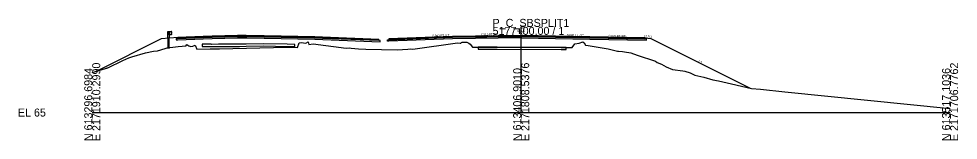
# Model space of a CAD drawing. Extents: x -26 to 1303, y -3010 to 12023.
# Drawn here: x -25.7 to 302.8, y 2990.3 to 3032.8 of the extents above; entities that cross this region are included whole.
import ezdxf

# ---------------------------------------------------------------- set-up
doc = ezdxf.new("R2010")
doc.units = 0
for name, color, linetype in [('RD_GPK_XS_Cell', 7, 'Continuous'), ('RD_PD_Final_TrvlWay', 7, 'Continuous'), ('RD_XS_Base', 7, 'Continuous'), ('RD_XS_ExGround', 7, 'Continuous'), ('RD_XS_ExPaveRet', 7, 'Continuous'), ('RD_XS_GR', 7, 'Continuous'), ('RD_XS_Greenside', 7, 'Continuous'), ('RD_XS_Pave', 7, 'Continuous'), ('RD_XS_PaveOvlay_CP', 7, 'Continuous'), ('RD_XS_TieSlope', 7, 'Continuous'), ('RD_XS_TX_Elev_EX', 7, 'Continuous'), ('RD_XS_TX_Elev_PR', 7, 'Continuous'), ('RD_XS_TX_ShdSlope', 7, 'Continuous'), ('RD_XS_TX_Slope', 7, 'Continuous')]:
    doc.layers.add(name, color=color, linetype=linetype)

msp = doc.modelspace()

# ---------------------------------------------------------------- linework, layer by layer
at = {"layer": 'RD_GPK_XS_Cell'}
for p, q in [((150, 3000), (150, 3030)), ((0, 3000), (150, 3000)), ((150, 3000), (300, 3000))]:
    msp.add_line(p, q, dxfattribs=at)
at = {"layer": 'RD_PD_Final_TrvlWay'}
for p, q in [((26.94, 3026.03), (26.44, 3025.99)), ((26.44, 3025.99), (26.44, 3022.43)), ((26.94, 3022.43), (26.94, 3026.03))]:
    msp.add_line(p, q, dxfattribs=at)
at = {"layer": 'RD_XS_Base'}
for p, q in [((29.75, 3025.95), (29.38, 3025.93)), ((29.38, 3025.93), (29.38, 3025.8)), ((29.38, 3025.8), (29.38, 3025.43)), ((29.88, 3025.95), (29.75, 3025.95)), ((38.75, 3026.31), (29.88, 3025.95)), ((29.88, 3025.45), (38.75, 3025.81)), ((41.88, 3026.43), (38.75, 3026.31)), ((38.75, 3025.81), (41.88, 3025.93)), ((50.75, 3026.61), (41.88, 3026.43)), ((41.88, 3025.93), (50.75, 3026.11)), ((53.88, 3026.67), (50.75, 3026.61)), ((50.75, 3026.11), (53.88, 3026.17)), ((53.88, 3026.79), (53.88, 3026.83)), ((53.88, 3026.83), (53.88, 3026.66)), ((53.88, 3026.67), (53.88, 3026.79)), ((53.88, 3026.54), (53.88, 3026.67)), ((60.14, 3026.55), (53.88, 3026.67)), ((53.88, 3026.66), (53.88, 3026.17)), ((53.88, 3026.17), (53.88, 3026.54)), ((53.88, 3026.17), (60.14, 3026.05)), ((77.88, 3026.19), (60.14, 3026.55)), ((60.14, 3026.05), (77.88, 3025.69)), ((80.49, 3026.09), (77.88, 3026.19)), ((100.21, 3025.3), (80.49, 3026.09)), ((103.74, 3025.46), (126, 3026.35)), ((126, 3025.85), (103.74, 3024.96)), ((126, 3026.35), (150.01, 3026.66)), ((126, 3026.35), (126, 3026.35)), ((150.01, 3026.16), (126, 3025.85)), ((126, 3025.85), (126, 3025.85)), ((150, 3026.66), (150, 3026.82)), ((150, 3026.82), (150, 3026.82)), ((150, 3026.82), (150, 3026.82)), ((150, 3026.82), (150, 3026.16)), ((150, 3026.66), (150, 3026.66)), ((162, 3026.42), (150, 3026.66)), ((150, 3026.66), (150, 3026.66)), ((150, 3026.66), (150, 3026.16)), ((150, 3026.16), (150, 3026.16)), ((150, 3026.16), (162, 3025.92)), ((174, 3026.18), (162, 3026.42)), ((162, 3026.42), (162, 3026.42)), ((162, 3025.92), (162, 3025.92)), ((162, 3025.92), (174, 3025.68)), ((193.3, 3025.8), (174, 3026.18)), ((174, 3026.18), (174, 3026.18)), ((193.8, 3025.79), (193.3, 3025.8)), ((193.3, 3025.8), (193.3, 3025.8)), ((193.8, 3025.29), (193.8, 3025.79)), ((193.8, 3025.79), (193.8, 3025.79)), ((29.38, 3025.43), (29.75, 3025.45)), ((29.75, 3025.45), (29.88, 3025.45)), ((77.88, 3025.69), (80.62, 3025.58)), ((80.62, 3025.58), (100.71, 3024.78)), ((100.34, 3025.29), (100.21, 3025.3)), ((100.71, 3025.28), (100.34, 3025.29)), ((100.71, 3025.15), (100.71, 3025.28)), ((100.71, 3024.78), (100.71, 3025.15)), ((103.24, 3025.44), (103.74, 3025.46)), ((103.24, 3024.94), (103.24, 3025.44)), ((103.24, 3025.44), (103.24, 3025.44)), ((103.74, 3024.96), (103.24, 3024.94)), ((103.24, 3024.94), (103.24, 3024.94)), ((103.24, 3024.94), (103.24, 3024.94)), ((103.74, 3025.46), (103.74, 3025.46)), ((103.74, 3024.96), (103.74, 3024.96)), ((174, 3025.68), (174, 3025.68)), ((174, 3025.68), (193.8, 3025.29))]:
    msp.add_line(p, q, dxfattribs=at)
at = {"layer": 'RD_XS_ExGround'}
msp.add_lwpolyline([(0, 3014.08), (4.65, 3015.43), (5.02, 3015.52), (5.09, 3015.55), (5.24, 3015.64), (5.45, 3015.7), (10.75, 3018.23), (12.84, 3019.16), (13.52, 3019.4), (13.83, 3019.51), (18.57, 3020.96), (21.41, 3021.47), (22.76, 3021.64), (25.49, 3022.44), (26.17, 3022.68), (29.08, 3023.06), (30.02, 3023.11), (32.83, 3023.34), (32.86, 3023.46), (33.13, 3023.79), (33.77, 3023.4), (34.47, 3023.08), (35.18, 3023.19), (36, 3023.59), (36.62, 3022.23), (41.25, 3022.34), (42.12, 3022.34), (44.54, 3022.33), (68.1, 3022.92), (70.89, 3022.85), (71.83, 3022.83), (72.33, 3024.47), (73.09, 3024.48), (74.65, 3024.34), (75.55, 3024.74), (75.74, 3023.81), (77.2, 3024.04), (88.77, 3022.6), (89.85, 3022.63), (90.6, 3022.54), (93.1, 3022.37), (95.69, 3022.14), (106.62, 3021.94), (110.36, 3022.15), (111.14, 3022.26), (112.1, 3022.21), (127.78, 3024.42), (128.61, 3024.35), (128.77, 3024.35), (128.81, 3024.35), (128.9, 3024.29), (129.14, 3024.56), (129.34, 3024.63), (129.75, 3024.66), (130.95, 3024.6), (131.42, 3024.43), (131.67, 3024.26), (132.14, 3023.93), (132.94, 3022.95), (137.76, 3022.92), (138.6, 3022.93), (141.57, 3022.95), (163.96, 3022.81), (167, 3022.82), (167.86, 3022.82), (168.77, 3024.11), (170.33, 3024.26), (171.51, 3024.8), (171.98, 3024.45), (172.52, 3023.57), (173.46, 3023.52), (180.45, 3022.3), (183.74, 3021.55), (184.04, 3021.55), (185.38, 3021.41), (186.08, 3021.22), (188.35, 3020.92), (190.59, 3020.13), (197.03, 3017.94), (197.58, 3017.53), (199.12, 3016.94), (200.7, 3015.96), (202.93, 3015.05), (206.5, 3014.58), (207.28, 3014.53), (209.12, 3013.9), (210.7, 3013.13), (213.87, 3012.43), (217.03, 3011.47), (219.03, 3011.05), (220.5, 3010.76), (223.51, 3010.03), (230.53, 3008.47), (233.64, 3008.15), (242.25, 3007.29), (300, 3001.43)], dxfattribs=at)
at = {"layer": 'RD_XS_ExPaveRet'}
for points in [[(68.2, 3023.92), (59.95, 3024.11), (53.83, 3023.96), (51.54, 3023.91), (44.1, 3023.92), (41.81, 3023.86), (41.61, 3023.92), (38.92, 3023.92), (38.47, 3023.91), (38.47, 3023.37), (38.47, 3023.16), (38.92, 3023.17), (41.61, 3023.17), (41.81, 3023.11), (44.1, 3023.17), (51.54, 3023.16), (53.83, 3023.21), (59.95, 3023.36), (68.2, 3023.17), (70.85, 3023.11), (70.85, 3023.32), (70.85, 3023.86), (68.2, 3023.92)], [(68.2, 3023.92), (59.95, 3024.11), (53.83, 3023.96), (51.54, 3023.91), (44.1, 3023.92), (41.81, 3023.86), (41.61, 3023.92), (38.92, 3023.92), (38.47, 3023.91), (38.47, 3023.37), (38.47, 3023.16), (38.92, 3023.17), (41.61, 3023.17), (41.81, 3023.11), (44.1, 3023.17), (51.54, 3023.16), (53.83, 3023.21), (59.95, 3023.36), (68.2, 3023.17), (70.85, 3023.11), (70.85, 3023.32), (70.85, 3023.86), (68.2, 3023.92)], [(163.96, 3022.81), (163.96, 3022.81), (141.57, 3022.95), (141.57, 3022.95), (141.57, 3022.95), (138.6, 3022.93), (137.76, 3022.92), (137.76, 3022.92), (134.92, 3022.94), (134.92, 3022.94), (134.92, 3022.94), (134.92, 3022.19), (134.92, 3022.19), (137.76, 3022.17), (137.76, 3022.17), (138.6, 3022.18), (141.57, 3022.2), (141.57, 3022.2), (141.57, 3022.2), (163.96, 3022.06), (163.96, 3022.06), (163.96, 3022.06), (165.68, 3022.07), (165.68, 3022.82), (165.68, 3022.82), (163.96, 3022.81), (163.96, 3022.81)], [(163.96, 3022.81), (141.57, 3022.95), (138.6, 3022.93), (137.76, 3022.92), (134.92, 3022.94), (134.92, 3022.19), (137.76, 3022.17), (138.6, 3022.18), (141.57, 3022.2), (163.96, 3022.06), (165.68, 3022.07), (165.68, 3022.82), (163.96, 3022.81)]]:
    msp.add_lwpolyline(points, dxfattribs=at)
at = {"layer": 'RD_XS_GR'}
for p, q in [((26.44, 3025.99), (26.44, 3028.43)), ((26.44, 3028.43), (26.69, 3028.43)), ((26.94, 3026.03), (26.44, 3025.99)), ((26.69, 3028.43), (26.94, 3028.43)), ((26.94, 3028.43), (26.94, 3026.03)), ((26.94, 3027.26), (26.94, 3028.43)), ((26.94, 3028.43), (27.61, 3028.43)), ((27.61, 3027.26), (26.94, 3027.26)), ((27.61, 3028.43), (27.61, 3027.26)), ((27.68, 3028.35), (27.61, 3028.43)), ((27.61, 3028.43), (27.61, 3028.12)), ((27.61, 3028.12), (27.61, 3027.26)), ((27.61, 3027.85), (27.81, 3028.06)), ((27.68, 3027.77), (27.61, 3027.85)), ((27.61, 3027.26), (27.81, 3027.48)), ((27.88, 3028.14), (27.68, 3028.35)), ((27.88, 3027.55), (27.68, 3027.77)), ((27.81, 3028.06), (27.88, 3028.14)), ((27.81, 3027.48), (27.88, 3027.55))]:
    msp.add_line(p, q, dxfattribs=at)
at = {"layer": 'RD_XS_Greenside'}
for p, q in [((24.13, 3025.81), (1.59, 3014.54)), ((195.3, 3025.96), (230.08, 3008.56))]:
    msp.add_line(p, q, dxfattribs=at)
at = {"layer": 'RD_XS_Pave'}
for p, q in [((38.75, 3026.62), (29.88, 3026.27)), ((38.75, 3026.46), (29.88, 3026.11)), ((29.88, 3026.11), (38.75, 3026.46)), ((29.88, 3025.95), (38.75, 3026.31)), ((29.88, 3026.27), (29.88, 3026.23)), ((29.88, 3026.23), (29.88, 3026.11)), ((29.88, 3026.11), (29.88, 3026.07)), ((29.88, 3026.07), (29.88, 3025.95)), ((41.88, 3026.75), (38.75, 3026.62)), ((41.88, 3026.59), (38.75, 3026.46)), ((38.75, 3026.46), (41.88, 3026.59)), ((38.75, 3026.31), (41.88, 3026.43)), ((50.75, 3026.93), (41.88, 3026.75)), ((50.75, 3026.77), (41.88, 3026.59)), ((41.88, 3026.59), (50.75, 3026.77)), ((41.88, 3026.43), (50.75, 3026.61)), ((53.88, 3026.99), (50.75, 3026.93)), ((53.88, 3026.83), (50.75, 3026.77)), ((50.75, 3026.77), (53.88, 3026.83)), ((50.75, 3026.61), (53.88, 3026.67)), ((60.14, 3026.86), (53.88, 3026.99)), ((53.88, 3026.79), (53.88, 3026.83)), ((53.88, 3026.83), (60.14, 3026.7)), ((60.14, 3026.7), (53.88, 3026.83)), ((53.88, 3026.83), (53.88, 3026.79)), ((53.88, 3026.67), (53.88, 3026.79)), ((53.88, 3026.79), (53.88, 3026.67)), ((53.88, 3026.67), (60.14, 3026.55)), ((77.88, 3026.51), (60.14, 3026.86)), ((60.14, 3026.7), (77.88, 3026.35)), ((77.88, 3026.35), (60.14, 3026.7)), ((60.14, 3026.55), (77.88, 3026.19)), ((80.49, 3026.4), (77.88, 3026.51)), ((77.88, 3026.35), (80.49, 3026.25)), ((80.49, 3026.25), (77.88, 3026.35)), ((77.88, 3026.19), (80.49, 3026.09)), ((100.21, 3025.62), (80.49, 3026.4)), ((80.49, 3026.25), (100.21, 3025.46)), ((100.21, 3025.46), (80.49, 3026.25)), ((80.49, 3026.09), (100.21, 3025.3)), ((126, 3026.67), (103.74, 3025.78)), ((126, 3026.51), (103.74, 3025.62)), ((103.74, 3025.62), (126, 3026.51)), ((103.74, 3025.46), (126, 3026.35)), ((150, 3026.98), (126, 3026.67)), ((150, 3026.82), (126, 3026.51)), ((126, 3026.51), (150, 3026.82)), ((126, 3026.67), (126, 3026.67)), ((126, 3026.51), (126, 3026.51)), ((126, 3026.51), (126, 3026.51)), ((126, 3026.35), (126, 3026.35)), ((126.01, 3026.35), (150.01, 3026.66)), ((162, 3026.74), (150, 3026.98)), ((150, 3026.98), (150, 3026.98)), ((150, 3026.66), (150, 3026.82)), ((150, 3026.82), (150, 3026.82)), ((150, 3026.82), (150, 3026.82)), ((150, 3026.82), (162, 3026.58)), ((162, 3026.58), (150, 3026.82)), ((150, 3026.82), (150, 3026.82)), ((150, 3026.82), (150, 3026.82)), ((150, 3026.82), (150, 3026.66)), ((150, 3026.66), (150, 3026.66)), ((150, 3026.66), (162, 3026.42)), ((174, 3026.5), (162, 3026.74)), ((162, 3026.74), (162, 3026.74)), ((162, 3026.58), (162, 3026.58)), ((162, 3026.58), (174, 3026.34)), ((174, 3026.34), (162, 3026.58)), ((162, 3026.58), (162, 3026.58)), ((162, 3026.42), (162, 3026.42)), ((162, 3026.42), (174, 3026.18)), ((193.3, 3026.12), (174, 3026.5)), ((174, 3026.5), (174, 3026.5)), ((174, 3026.34), (174, 3026.34)), ((174, 3026.34), (193.3, 3025.96)), ((193.3, 3025.96), (174, 3026.34)), ((174, 3026.34), (174, 3026.34)), ((174, 3026.18), (193.3, 3025.8)), ((174, 3026.18), (174, 3026.18)), ((193.3, 3025.96), (193.3, 3026.12)), ((193.3, 3026.12), (193.3, 3026.12)), ((193.3, 3025.8), (193.3, 3025.96)), ((193.3, 3025.96), (193.3, 3025.96)), ((100.21, 3025.57), (100.21, 3025.62)), ((100.21, 3025.46), (100.21, 3025.57)), ((100.21, 3025.42), (100.21, 3025.46)), ((100.21, 3025.3), (100.21, 3025.42)), ((103.74, 3025.78), (103.74, 3025.78)), ((103.74, 3025.78), (103.74, 3025.62)), ((103.74, 3025.62), (103.74, 3025.62)), ((103.74, 3025.62), (103.74, 3025.46)), ((103.74, 3025.62), (103.74, 3025.62)), ((103.74, 3025.62), (103.74, 3025.62)), ((103.74, 3025.46), (103.74, 3025.46)), ((103.74, 3025.46), (103.74, 3025.46))]:
    msp.add_line(p, q, dxfattribs=at)
at = {"layer": 'RD_XS_PaveOvlay_CP'}
for p, q in [((29.88, 3026.27), (41.88, 3026.75)), ((41.88, 3026.75), (53.88, 3026.99)), ((53.88, 3026.99), (77.88, 3026.51)), ((77.88, 3026.51), (100.21, 3025.62)), ((126, 3026.67), (103.74, 3025.78)), ((150, 3026.98), (126, 3026.67)), ((126, 3026.67), (126, 3026.67)), ((162, 3026.74), (150, 3026.98)), ((150, 3026.98), (150, 3026.98)), ((174, 3026.5), (162, 3026.74)), ((162, 3026.74), (162, 3026.74)), ((193.3, 3026.12), (174, 3026.5)), ((174, 3026.5), (174, 3026.5)), ((103.74, 3025.78), (103.74, 3025.78))]:
    msp.add_line(p, q, dxfattribs=at)
at = {"layer": 'RD_XS_TieSlope'}
for p, q in [((29.88, 3026.27), (24.13, 3025.81)), ((193.3, 3026.12), (195.3, 3025.96))]:
    msp.add_line(p, q, dxfattribs=at)

# ---------------------------------------------------------------- texts
at = {"layer": 'RD_GPK_XS_Cell'}
for s, p in [('P_C_SBSPLIT1', (140, 3030)), ('5177+00.00 / 1', (140, 3027.2)), ('EL 65', (-26, 2998.6))]:
    msp.add_text(s, height=2.8, dxfattribs=at).set_placement(p)
for s, p in [('E 2171910.2990', (2.8, 2990)), ('E 2171808.5376', (152.8, 2990)), ('E 2171706.7762', (302.8, 2990)), ('N 613296.6984', (0, 2990)), ('N 613406.9010', (150, 2990)), ('N 613517.1036', (300, 2990))]:
    msp.add_text(s, height=2.8, rotation=90, dxfattribs=at).set_placement(p)
at = {"layer": 'RD_XS_TX_Elev_EX'}
msp.add_text('88.61', height=0.6, rotation=90, dxfattribs=at).set_placement((149.74, 3027.63))
at = {"layer": 'RD_XS_TX_Elev_PR'}
msp.add_text('91.98', height=1, rotation=90, dxfattribs=at).set_placement((151.17, 3027.28))
at = {"layer": 'RD_XS_TX_ShdSlope'}
msp.add_text('12.5:1', height=0.75, rotation=355.4261, dxfattribs=at).set_placement((192.84, 3026.43))
at = {"layer": 'RD_XS_TX_Slope'}
for s, rotation, p in [('0.040 FT./FT.', 2.2906, (118.94, 3026.49)), ('0.013 FT./FT.', 1.1524, (135.94, 3027)), ('0.020 FT./FT.', 358.8542, (165.94, 3026.76)), ('0.020 FT./FT.', 358.8542, (180.59, 3026.47)), ('2:1', 333.4349, (211.8, 3017.77))]:
    msp.add_text(s, height=0.75, rotation=rotation, dxfattribs=at).set_placement(p)

doc.saveas('drawing.dxf')
